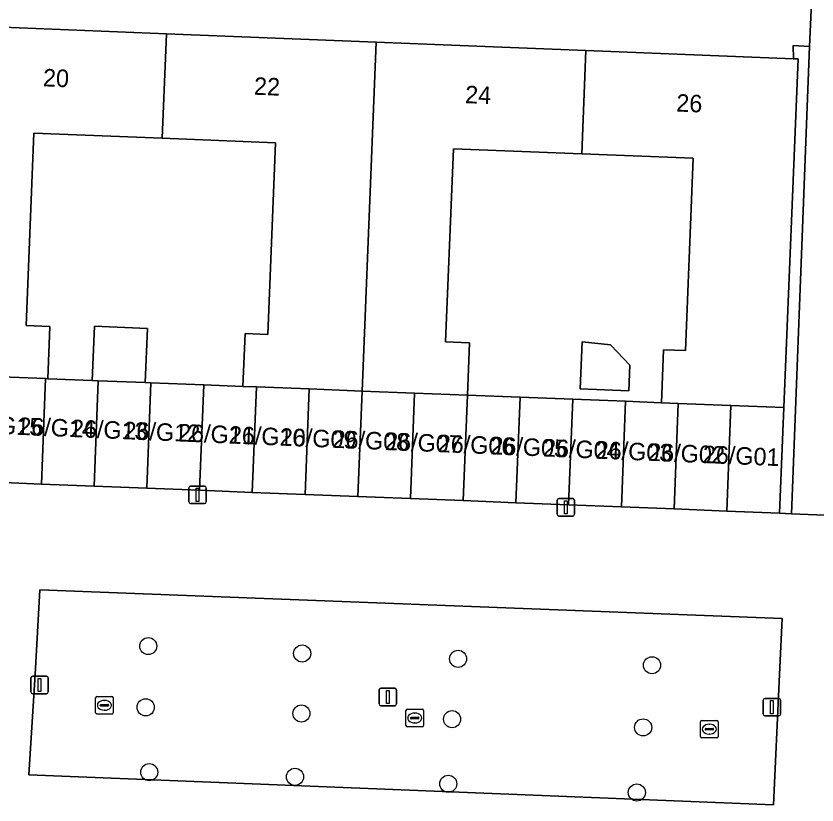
# Model space of a CAD drawing. Extents: x 160786 to 161429, y 386828 to 387485.
# Drawn here: x 161190.84 to 161236.62, y 386992.54 to 387037.64 of the extents above; entities that cross this region are included whole.
import ezdxf

# ---------------------------------------------------------------- set-up
doc = ezdxf.new("R2010")
doc.units = 0
for name, color, linetype in [('IMGEO_Boom', 7, 'Continuous'), ('IMGEO_Erf', 7, 'Continuous'), ('IMGEO_Groenvoorziening', 7, 'Continuous'), ('IMGEO_Kolk', 7, 'Continuous'), ('IMGEO_Lichtmast', 7, 'Continuous'), ('IMGEO_Pand', 7, 'Continuous'), ('IMGEO_Pand_nummerreeks', 7, 'Continuous'), ('IMGEO_Parkeervlak_open', 7, 'Continuous'), ('IMGEO_Rijbaan_lokaal_open', 7, 'Continuous'), ('IMGEO_Voetpad_open', 7, 'Continuous')]:
    doc.layers.add(name, color=color, linetype=linetype)

msp = doc.modelspace()

# ---------------------------------------------------------------- linework, layer by layer
at = {"layer": 'IMGEO_Boom'}
for centre in [(161198.399, 387001.625), (161207.196, 387001.204), (161216.107, 387000.897), (161227.189, 387000.532), (161198.254, 386998.128), (161207.154, 386997.771), (161215.762, 386997.451), (161226.68, 386996.979), (161198.456, 386994.421), (161206.784, 386994.152), (161215.544, 386993.757), (161226.323, 386993.259)]:
    msp.add_circle(centre, 0.489, dxfattribs=at)
at = {"layer": 'IMGEO_Erf'}
for points in [[(161205.678, 387030.395), (161199.197, 387030.653), (161191.858, 387030.946), (161191.419, 387019.944), (161192.774, 387019.89), (161192.656, 387016.908), (161195.202, 387016.808), (161195.323, 387019.903), (161198.353, 387019.785), (161198.232, 387016.69), (161198.557, 387016.677), (161201.57, 387016.559), (161203.814, 387016.471), (161203.934, 387019.486), (161205.241, 387019.434)], [(161229.546, 387029.507), (161223.171, 387029.761), (161215.835, 387030.053), (161215.395, 387019.007), (161216.755, 387018.953), (161216.636, 387015.962), (161219.648, 387015.847), (161222.662, 387015.731), (161225.675, 387015.615), (161227.722, 387015.537), (161227.842, 387018.563), (161229.108, 387018.513)], [(161223.196, 387019.01), (161224.822, 387018.843), (161225.913, 387017.681), (161225.856, 387016.217), (161223.09, 387016.326)]]:
    msp.add_lwpolyline(points, close=True, dxfattribs=at)
at = {"layer": 'IMGEO_Groenvoorziening'}
msp.add_lwpolyline([(161235.161, 387009.191), (161236.191, 387035.895), (161235.263, 387035.944), (161235.27, 387035.194), (161235.548, 387035.183), (161234.725, 387015.253), (161234.476, 387009.225)], close=True, dxfattribs=at)
at = {"layer": 'IMGEO_Kolk'}
for p, q in [((161195.393, 386997.818), (161195.393, 386998.67)), ((161195.468, 386998.744), (161196.32, 386998.744)), ((161195.881, 386998.524), (161195.906, 386998.524)), ((161196.394, 386998.67), (161196.394, 386997.818)), ((161195.652, 386998.238), (161195.652, 386998.25)), ((161196.09, 386998.201), (161195.692, 386998.201)), ((161195.695, 386998.287), (161196.093, 386998.287)), ((161195.904, 386997.964), (161195.879, 386997.964)), ((161196.136, 386998.25), (161196.136, 386998.238)), ((161213.129, 386997.09), (161213.129, 386997.942)), ((161213.204, 386998.016), (161214.056, 386998.016)), ((161214.13, 386997.942), (161214.13, 386997.09)), ((161196.32, 386997.744), (161195.468, 386997.744)), ((161213.388, 386997.51), (161213.388, 386997.522)), ((161213.826, 386997.473), (161213.428, 386997.473)), ((161213.431, 386997.559), (161213.829, 386997.559)), ((161213.617, 386997.796), (161213.642, 386997.796)), ((161213.872, 386997.522), (161213.872, 386997.51)), ((161214.056, 386997.016), (161213.204, 386997.016)), ((161213.64, 386997.236), (161213.615, 386997.236)), ((161229.964, 386996.452), (161229.964, 386997.304)), ((161230.039, 386997.378), (161230.891, 386997.378)), ((161230.452, 386997.158), (161230.477, 386997.158)), ((161230.965, 386997.304), (161230.965, 386996.452)), ((161230.223, 386996.872), (161230.223, 386996.884)), ((161230.661, 386996.835), (161230.263, 386996.835)), ((161230.266, 386996.921), (161230.664, 386996.921)), ((161230.475, 386996.598), (161230.45, 386996.598)), ((161230.707, 386996.884), (161230.707, 386996.872)), ((161230.891, 386996.378), (161230.039, 386996.378))]:
    msp.add_line(p, q, dxfattribs=at)
for points in [[(161195.393, 386997.818), (161195.393, 386998.67)], [(161195.468, 386998.744), (161196.32, 386998.744)], [(161196.394, 386998.67), (161196.394, 386997.818)], [(161213.129, 386997.09), (161213.129, 386997.942)], [(161213.204, 386998.016), (161214.056, 386998.016)], [(161214.13, 386997.942), (161214.13, 386997.09)], [(161196.32, 386997.744), (161195.468, 386997.744)], [(161214.056, 386997.016), (161213.204, 386997.016)], [(161229.964, 386996.452), (161229.964, 386997.304)], [(161230.039, 386997.378), (161230.891, 386997.378)], [(161230.965, 386997.304), (161230.965, 386996.452)], [(161230.891, 386996.378), (161230.039, 386996.378)]]:
    msp.add_lwpolyline(points, dxfattribs=at)
for centre, radius, start, end in [((161195.47, 386998.668), 0.0765, 91.552, 178.448), ((161195.47, 386998.668), 0.0765, 91.552, 178.448), ((161196.318, 386998.668), 0.0765, 1.552, 88.448), ((161196.318, 386998.668), 0.0765, 1.552, 88.448), ((161195.692, 386998.247), 0.0403, 85.8775, 175.7526), ((161195.689, 386998.237), 0.0366, 178.938, 274.7102), ((161196.093, 386998.244), 0.043, 264.8664, 352.4533), ((161196.097, 386998.249), 0.0386, 1.7309, 96.639), ((161213.206, 386997.94), 0.0765, 91.552, 178.448), ((161213.206, 386997.94), 0.0765, 91.552, 178.448), ((161214.054, 386997.94), 0.0765, 1.552, 88.448), ((161214.054, 386997.94), 0.0765, 1.552, 88.448), ((161195.47, 386997.82), 0.0765, 181.552, 268.448), ((161195.47, 386997.82), 0.0765, 181.552, 268.448), ((161196.318, 386997.82), 0.0765, 271.552, 358.448), ((161196.318, 386997.82), 0.0765, 271.552, 358.448), ((161213.428, 386997.519), 0.0403, 85.8775, 175.7526), ((161213.425, 386997.509), 0.0366, 178.938, 274.7102), ((161213.829, 386997.516), 0.043, 264.8664, 352.4533), ((161213.833, 386997.521), 0.0386, 1.7309, 96.639), ((161213.206, 386997.092), 0.0765, 181.552, 268.448), ((161213.206, 386997.092), 0.0765, 181.552, 268.448), ((161214.054, 386997.092), 0.0765, 271.552, 358.448), ((161214.054, 386997.092), 0.0765, 271.552, 358.448), ((161230.041, 386997.302), 0.0765, 91.552, 178.448), ((161230.041, 386997.302), 0.0765, 91.552, 178.448), ((161230.889, 386997.302), 0.0765, 1.552, 88.448), ((161230.889, 386997.302), 0.0765, 1.552, 88.448), ((161230.263, 386996.881), 0.0403, 85.8775, 175.7526), ((161230.26, 386996.871), 0.0366, 178.938, 274.7102), ((161230.664, 386996.878), 0.043, 264.8664, 352.4533), ((161230.668, 386996.883), 0.0386, 1.7309, 96.639), ((161230.041, 386996.454), 0.0765, 181.552, 268.448), ((161230.041, 386996.454), 0.0765, 181.552, 268.448), ((161230.889, 386996.454), 0.0765, 271.552, 358.448), ((161230.889, 386996.454), 0.0765, 271.552, 358.448)]:
    msp.add_arc(centre, radius, start, end, dxfattribs=at)
for centre, major_axis, ratio, start_param, end_param in [((161195.88, 386998.244), (-0.387, 0.002), 0.722429, 4.712389, 7.853982), ((161195.905, 386998.244), (-0.39, 0.002), 0.717154, 1.570796, 4.712389), ((161213.616, 386997.516), (-0.387, 0.002), 0.722429, 4.712389, 7.853982), ((161213.641, 386997.516), (-0.39, 0.002), 0.717154, 1.570796, 4.712389), ((161230.451, 386996.878), (-0.387, 0.002), 0.722429, 4.712389, 7.853982), ((161230.476, 386996.878), (-0.39, 0.002), 0.717154, 1.570796, 4.712389)]:
    msp.add_ellipse(centre, major_axis=major_axis, ratio=ratio, start_param=start_param, end_param=end_param, dxfattribs=at)
at = {"layer": 'IMGEO_Lichtmast'}
for p, q in [((161200.722, 387009.868), (161200.722, 387010.668)), ((161200.722, 387010.668), (161200.722, 387009.868)), ((161200.822, 387010.768), (161201.612, 387010.768)), ((161201.612, 387010.768), (161200.822, 387010.768)), ((161201.712, 387010.668), (161201.712, 387009.868)), ((161201.712, 387009.868), (161201.712, 387010.668)), ((161201.612, 387009.768), (161200.822, 387009.768)), ((161200.822, 387009.768), (161201.612, 387009.768)), ((161221.767, 387009.159), (161221.767, 387009.959)), ((161221.767, 387009.959), (161221.767, 387009.159)), ((161221.867, 387010.059), (161222.657, 387010.059)), ((161222.657, 387010.059), (161221.867, 387010.059)), ((161222.757, 387009.959), (161222.757, 387009.159)), ((161222.757, 387009.159), (161222.757, 387009.959)), ((161222.657, 387009.059), (161221.867, 387009.059)), ((161221.867, 387009.059), (161222.657, 387009.059)), ((161191.697, 386999.005), (161191.697, 386999.805)), ((161191.697, 386999.805), (161191.697, 386999.005)), ((161191.797, 386999.905), (161192.587, 386999.905)), ((161192.587, 386999.905), (161191.797, 386999.905)), ((161192.687, 386999.805), (161192.687, 386999.005)), ((161192.687, 386999.005), (161192.687, 386999.805)), ((161211.695, 386999.22), (161212.485, 386999.22)), ((161212.485, 386999.22), (161211.695, 386999.22)), ((161192.587, 386998.905), (161191.797, 386998.905)), ((161191.797, 386998.905), (161192.587, 386998.905)), ((161211.595, 386998.32), (161211.595, 386999.12)), ((161211.595, 386999.12), (161211.595, 386998.32)), ((161212.585, 386999.12), (161212.585, 386998.32)), ((161212.585, 386998.32), (161212.585, 386999.12)), ((161233.545, 386997.735), (161233.545, 386998.535)), ((161233.545, 386998.535), (161233.545, 386997.735)), ((161233.645, 386998.635), (161234.435, 386998.635)), ((161234.435, 386998.635), (161233.645, 386998.635)), ((161234.535, 386998.535), (161234.535, 386997.735)), ((161234.535, 386997.735), (161234.535, 386998.535)), ((161212.485, 386998.22), (161211.695, 386998.22)), ((161211.695, 386998.22), (161212.485, 386998.22)), ((161234.435, 386997.635), (161233.645, 386997.635)), ((161233.645, 386997.635), (161234.435, 386997.635))]:
    msp.add_line(p, q, dxfattribs=at)
for points in [[(161201.142, 387010.643), (161201.292, 387010.643), (161201.292, 387009.893), (161201.142, 387009.893), (161201.142, 387010.643)], [(161222.187, 387009.934), (161222.337, 387009.934), (161222.337, 387009.184), (161222.187, 387009.184), (161222.187, 387009.934)], [(161192.117, 386999.78), (161192.267, 386999.78), (161192.267, 386999.03), (161192.117, 386999.03), (161192.117, 386999.78)], [(161212.015, 386999.095), (161212.165, 386999.095), (161212.165, 386998.345), (161212.015, 386998.345), (161212.015, 386999.095)], [(161233.965, 386998.51), (161234.115, 386998.51), (161234.115, 386997.76), (161233.965, 386997.76), (161233.965, 386998.51)]]:
    msp.add_lwpolyline(points, dxfattribs=at)
for centre, start, end in [((161200.822, 387010.668), 90, 180), ((161200.822, 387010.668), 90, 180), ((161201.612, 387010.668), 0, 90), ((161201.612, 387010.668), 360, 90), ((161200.822, 387009.868), 180, 270), ((161200.822, 387009.868), 180, 270), ((161201.612, 387009.868), 270, 0), ((161201.612, 387009.868), 270, 0), ((161221.867, 387009.959), 90, 180), ((161221.867, 387009.959), 90, 180), ((161222.657, 387009.959), 0, 90), ((161222.657, 387009.959), 360, 90), ((161221.867, 387009.159), 180, 270), ((161221.867, 387009.159), 180, 270), ((161222.657, 387009.159), 270, 0), ((161222.657, 387009.159), 270, 0), ((161191.797, 386999.805), 90, 180), ((161191.797, 386999.805), 90, 180), ((161192.587, 386999.805), 0, 90), ((161192.587, 386999.805), 360, 90), ((161211.695, 386999.12), 90, 180), ((161211.695, 386999.12), 90, 180), ((161212.485, 386999.12), 0, 90), ((161212.485, 386999.12), 360, 90), ((161191.797, 386999.005), 180, 270), ((161191.797, 386999.005), 180, 270), ((161192.587, 386999.005), 270, 0), ((161192.587, 386999.005), 270, 0), ((161211.695, 386998.32), 180, 270), ((161211.695, 386998.32), 180, 270), ((161212.485, 386998.32), 270, 0), ((161212.485, 386998.32), 270, 0), ((161233.645, 386998.535), 90, 180), ((161233.645, 386998.535), 90, 180), ((161234.435, 386998.535), 0, 90), ((161234.435, 386998.535), 360, 90), ((161233.645, 386997.735), 180, 270), ((161233.645, 386997.735), 180, 270), ((161234.435, 386997.735), 270, 0), ((161234.435, 386997.735), 270, 0)]:
    msp.add_arc(centre, 0.1, start, end, dxfattribs=at)
at = {"layer": 'IMGEO_Pand'}
for points in [[(161187.289, 387037.106), (161186.504, 387017.154), (161189.518, 387017.033), (161192.531, 387016.913), (161192.656, 387016.908), (161192.774, 387019.89), (161191.419, 387019.944), (161191.858, 387030.946), (161199.197, 387030.653), (161199.435, 387036.622)], [(161199.435, 387036.622), (161199.197, 387030.653), (161205.678, 387030.395), (161205.241, 387019.434), (161203.934, 387019.486), (161203.814, 387016.471), (161204.583, 387016.441), (161207.596, 387016.322), (161210.633, 387016.202), (161211.42, 387036.144)], [(161211.42, 387036.144), (161210.633, 387016.202), (161213.622, 387016.082), (161216.636, 387015.962), (161216.755, 387018.953), (161215.395, 387019.007), (161215.835, 387030.053), (161223.171, 387029.761), (161223.406, 387035.667)], [(161223.406, 387035.667), (161223.171, 387029.761), (161229.546, 387029.507), (161229.108, 387018.513), (161227.842, 387018.563), (161227.722, 387015.537), (161228.688, 387015.498), (161231.701, 387015.376), (161234.725, 387015.253), (161235.548, 387035.183), (161235.27, 387035.194)], [(161195.202, 387016.808), (161195.544, 387016.795), (161198.232, 387016.69), (161198.353, 387019.785), (161195.323, 387019.903)], [(161223.196, 387019.01), (161223.09, 387016.326), (161225.856, 387016.217), (161225.913, 387017.681), (161224.822, 387018.843)], [(161189.28, 387011.007), (161192.293, 387010.888), (161192.531, 387016.913), (161189.518, 387017.033)], [(161195.544, 387016.795), (161195.202, 387016.808), (161192.656, 387016.908), (161192.531, 387016.913), (161192.293, 387010.888), (161195.306, 387010.77)], [(161198.557, 387016.677), (161198.232, 387016.69), (161195.544, 387016.795), (161195.306, 387010.77), (161198.319, 387010.651)], [(161201.57, 387016.559), (161198.557, 387016.677), (161198.319, 387010.651), (161201.332, 387010.532)], [(161201.332, 387010.532), (161204.345, 387010.413), (161204.583, 387016.441), (161203.814, 387016.471), (161201.57, 387016.559)], [(161207.596, 387016.322), (161204.583, 387016.441), (161204.345, 387010.413), (161207.358, 387010.294)], [(161210.633, 387016.202), (161207.596, 387016.322), (161207.358, 387010.294), (161210.372, 387010.175)], [(161213.622, 387016.082), (161210.633, 387016.202), (161210.372, 387010.175), (161213.385, 387010.057)], [(161213.385, 387010.057), (161216.398, 387009.938), (161216.636, 387015.962), (161213.622, 387016.082)], [(161216.398, 387009.938), (161219.411, 387009.819), (161219.648, 387015.847), (161216.636, 387015.962)], [(161219.411, 387009.819), (161222.424, 387009.7), (161222.662, 387015.731), (161219.648, 387015.847)], [(161225.675, 387015.615), (161222.662, 387015.731), (161222.424, 387009.7), (161225.437, 387009.581)], [(161225.437, 387009.581), (161228.45, 387009.463), (161228.688, 387015.498), (161227.722, 387015.537), (161225.675, 387015.615)], [(161231.701, 387015.376), (161228.688, 387015.498), (161228.45, 387009.463), (161231.463, 387009.344)], [(161234.725, 387015.253), (161231.701, 387015.376), (161231.463, 387009.344), (161234.476, 387009.225)]]:
    msp.add_lwpolyline(points, close=True, dxfattribs=at)
at = {"layer": 'IMGEO_Parkeervlak_open'}
msp.add_lwpolyline([(161234.129, 386992.545), (161234.483, 387000), (161234.619, 387003.196), (161192.201, 387004.843), (161191.944, 387000), (161191.567, 386994.261)], close=True, dxfattribs=at)
at = {"layer": 'IMGEO_Rijbaan_lokaal_open'}
msp.add_lwpolyline([(161237.546, 387009.09), (161235.161, 387009.191), (161234.476, 387009.225), (161231.463, 387009.344), (161228.45, 387009.463), (161225.437, 387009.581), (161222.424, 387009.7), (161219.411, 387009.819), (161216.398, 387009.938), (161213.385, 387010.057), (161210.372, 387010.175), (161207.358, 387010.294), (161204.345, 387010.413), (161201.332, 387010.532), (161198.319, 387010.651), (161195.306, 387010.77), (161192.293, 387010.888), (161189.28, 387011.007)], dxfattribs=at)
msp.add_lwpolyline([(161234.619, 387003.196), (161234.483, 387000), (161234.129, 386992.545), (161191.567, 386994.261), (161191.944, 387000), (161192.201, 387004.843)], close=True, dxfattribs=at)
at = {"layer": 'IMGEO_Voetpad_open'}
for points in [[(161239.655, 387061.146), (161237.164, 387061.255), (161236.536, 387044.01), (161236.438, 387041.325), (161236.191, 387035.895), (161235.161, 387009.191), (161237.546, 387009.09)], [(161236.438, 387041.325), (161230.575, 387041.539), (161229.576, 387041.576), (161217.795, 387042.006), (161216.796, 387042.043), (161206.615, 387042.415), (161205.616, 387042.451), (161193.813, 387042.882), (161192.814, 387042.919), (161187.174, 387043.125), (161186.979, 387037.128), (161187.289, 387037.106), (161199.435, 387036.622), (161211.42, 387036.144), (161223.406, 387035.667), (161235.27, 387035.194), (161235.263, 387035.944), (161236.191, 387035.895)]]:
    msp.add_lwpolyline(points, close=True, dxfattribs=at)

# ---------------------------------------------------------------- texts
at = {"layer": 'IMGEO_Pand_nummerreeks'}
for s, rotation, p in [('20', 357.7181, (161192.368, 387033.621)), ('22', 357.7181, (161204.427, 387033.14)), ('24', 357.7181, (161216.494, 387032.659)), ('26', 357.7181, (161228.559, 387032.179)), ('26/G15', 357.645, (161187.946, 387013.825)), ('26/G14', 357.6451, (161190.954, 387013.701)), ('26/G13', 357.6451, (161193.962, 387013.578)), ('26/G12', 357.645, (161196.963, 387013.454)), ('26/G11', 357.645, (161200.087, 387013.325)), ('26/G10', 357.645, (161202.988, 387013.206)), ('26/G09', 357.645, (161205.899, 387013.087)), ('26/G08', 357.645, (161208.913, 387012.963)), ('26/G07', 357.645, (161211.917, 387012.839)), ('26/G06', 357.645, (161214.925, 387012.715)), ('26/G05', 357.645, (161217.933, 387012.592)), ('26/G04', 357.645, (161220.941, 387012.468)), ('26/G03', 357.645, (161223.949, 387012.344)), ('26/G02', 357.645, (161226.95, 387012.221)), ('26/G01', 357.645, (161230.074, 387012.092))]:
    msp.add_text(s, height=1, rotation=rotation, dxfattribs=at).set_placement(p)

doc.saveas('drawing.dxf')
